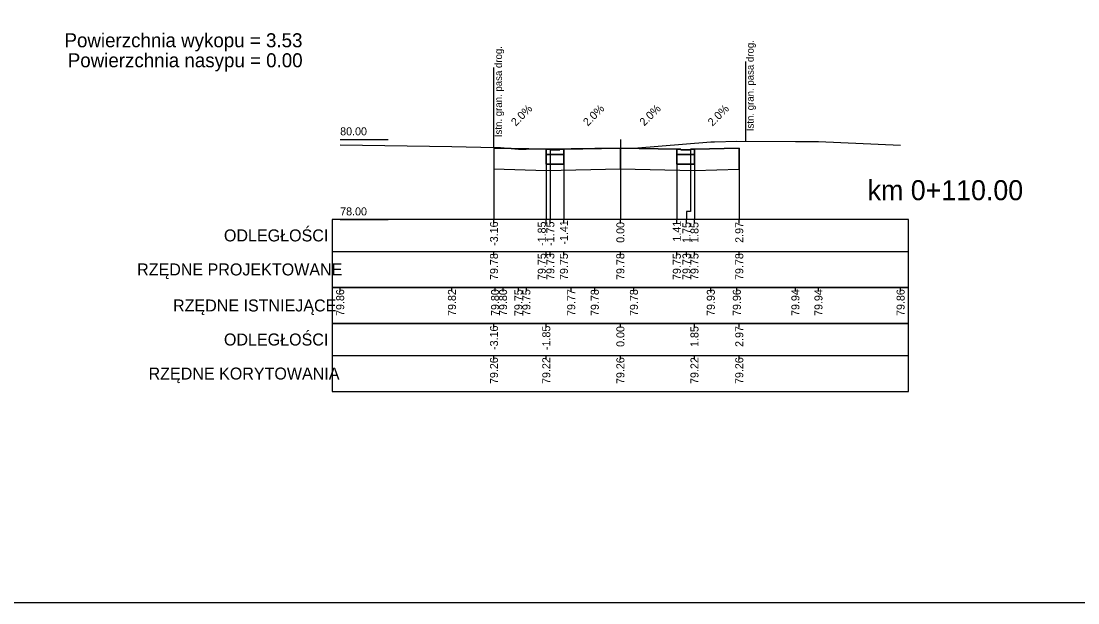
# Model space of a CAD drawing. Extents: x 7492871 to 7493499, y 5802964 to 5802992.
# Drawn here: x 7492929.58 to 7492955.98, y 5802963.88 to 5802978.41 of the extents above; entities that cross this region are included whole.
import ezdxf

# ---------------------------------------------------------------- set-up
doc = ezdxf.new("R2010")
doc.units = 0
for name, color, linetype in [('_wydruk', 7, 'Continuous'), ('d_pop_nasyp_opis', 7, 'Continuous'), ('d_pop_wykop_opis', 7, 'Continuous'), ('opisy_ramki_pop', 7, 'Continuous'), ('pop_comp_kostka', 7, 'Continuous'), ('pop_comp_lawa', 7, 'Continuous'), ('pop_comp_scieralna', 7, 'Continuous'), ('pop_granica_istn', 7, 'Continuous'), ('pop_opis', 7, 'Continuous'), ('pop_os', 7, 'Continuous'), ('pop_pikietaz', 7, 'Continuous'), ('pop_teren', 7, 'Continuous')]:
    doc.layers.add(name, color=color, linetype=linetype)

msp = doc.modelspace()

# ---------------------------------------------------------------- linework, layer by layer
msp.add_lwpolyline([(7492941.389, 5802975.239), (7492942.696, 5802975.213), (7492942.796, 5802975.213), (7492942.797, 5802975.193), (7492943.036, 5802975.193), (7492943.037, 5802975.213), (7492943.137, 5802975.213), (7492944.547, 5802975.241), (7492945.957, 5802975.213), (7492946.057, 5802975.213), (7492946.058, 5802975.193), (7492946.297, 5802975.193), (7492946.298, 5802975.213), (7492946.398, 5802975.213), (7492947.517, 5802975.235)])
at = {"layer": '_wydruk'}
msp.add_lwpolyline([(7492871.369, 5802992.281), (7493499.283, 5802992.281), (7493499.283, 5802963.881), (7492871.369, 5802963.881)], close=True, dxfattribs=at)
at = {"layer": 'opisy_ramki_pop'}
for points in [[(7492941.389, 5802974.719), (7492941.389, 5802973.659), (7492941.389, 5802973.659), (7492941.389, 5802973.459)], [(7492942.696, 5802974.684), (7492942.696, 5802973.659), (7492942.696, 5802973.659), (7492942.696, 5802973.459)], [(7492944.547, 5802974.721), (7492944.547, 5802973.659), (7492944.547, 5802973.659), (7492944.547, 5802973.459)], [(7492946.398, 5802974.684), (7492946.398, 5802973.659), (7492946.398, 5802973.659), (7492946.398, 5802973.459)], [(7492947.517, 5802974.715), (7492947.517, 5802973.659), (7492947.517, 5802973.659), (7492947.517, 5802973.459)]]:
    msp.add_lwpolyline(points, dxfattribs=at)
at = {"layer": 'pop_comp_kostka'}
for p, q in [((7492942.796, 5802975.213), (7492942.696, 5802975.213)), ((7492942.696, 5802975.213), (7492942.696, 5802975.083)), ((7492942.797, 5802975.193), (7492942.796, 5802975.213)), ((7492943.037, 5802975.213), (7492943.036, 5802975.193)), ((7492943.137, 5802975.213), (7492943.037, 5802975.213)), ((7492943.137, 5802975.083), (7492943.137, 5802975.213)), ((7492946.057, 5802975.213), (7492945.957, 5802975.213)), ((7492945.957, 5802975.213), (7492945.957, 5802975.083)), ((7492946.058, 5802975.193), (7492946.057, 5802975.213)), ((7492946.298, 5802975.213), (7492946.297, 5802975.193)), ((7492946.398, 5802975.213), (7492946.298, 5802975.213)), ((7492946.398, 5802975.083), (7492946.398, 5802975.213)), ((7492942.696, 5802975.083), (7492943.137, 5802975.083)), ((7492943.036, 5802975.193), (7492942.797, 5802975.193)), ((7492945.957, 5802975.083), (7492946.398, 5802975.083)), ((7492946.297, 5802975.193), (7492946.058, 5802975.193))]:
    msp.add_line(p, q, dxfattribs=at)
at = {"layer": 'pop_comp_lawa'}
for p, q in [((7492943.137, 5802975.083), (7492942.696, 5802975.083)), ((7492942.696, 5802975.083), (7492942.696, 5802974.842)), ((7492943.137, 5802974.842), (7492943.137, 5802975.083)), ((7492946.398, 5802975.083), (7492945.957, 5802975.083)), ((7492945.957, 5802975.083), (7492945.957, 5802974.842)), ((7492946.398, 5802974.842), (7492946.398, 5802975.083)), ((7492942.696, 5802974.842), (7492943.137, 5802974.842)), ((7492945.957, 5802974.842), (7492946.398, 5802974.842))]:
    msp.add_line(p, q, dxfattribs=at)
at = {"layer": 'pop_comp_scieralna'}
for p, q in [((7492942.696, 5802975.213), (7492941.389, 5802975.239)), ((7492941.389, 5802975.239), (7492941.389, 5802974.719)), ((7492942.696, 5802974.842), (7492942.696, 5802975.213)), ((7492944.547, 5802975.241), (7492943.137, 5802975.213)), ((7492943.137, 5802975.213), (7492943.137, 5802974.842)), ((7492944.547, 5802974.721), (7492944.547, 5802975.241)), ((7492945.957, 5802975.213), (7492944.547, 5802975.241)), ((7492944.547, 5802975.241), (7492944.547, 5802974.721)), ((7492945.957, 5802974.842), (7492945.957, 5802975.213)), ((7492947.517, 5802975.235), (7492946.398, 5802975.213)), ((7492946.398, 5802975.213), (7492946.398, 5802974.842)), ((7492947.517, 5802974.715), (7492947.517, 5802975.235)), ((7492941.389, 5802974.719), (7492942.696, 5802974.684)), ((7492943.137, 5802974.842), (7492942.696, 5802974.842)), ((7492942.696, 5802974.684), (7492944.547, 5802974.721)), ((7492944.547, 5802974.721), (7492946.398, 5802974.684)), ((7492946.398, 5802974.842), (7492945.957, 5802974.842)), ((7492946.398, 5802974.684), (7492947.517, 5802974.715))]:
    msp.add_line(p, q, dxfattribs=at)
at = {"layer": 'pop_granica_istn'}
for p, q in [((7492947.68, 5802975.902), (7492947.68, 5802977.402)), ((7492941.389, 5802975.753), (7492941.389, 5802977.253)), ((7492941.389, 5802975.253), (7492941.389, 5802975.753)), ((7492947.68, 5802975.402), (7492947.68, 5802975.902))]:
    msp.add_line(p, q, dxfattribs=at)
at = {"layer": 'pop_opis'}
for p, q in [((7492937.547, 5802975.459), (7492938.747, 5802975.459)), ((7492937.347, 5802973.459), (7492937.347, 5802971.759)), ((7492937.347, 5802973.459), (7492937.347, 5802971.759)), ((7492937.347, 5802973.459), (7492937.347, 5802971.759)), ((7492937.347, 5802973.459), (7492937.347, 5802971.759)), ((7492937.547, 5802973.459), (7492938.747, 5802973.459)), ((7492941.389, 5802973.359), (7492941.389, 5802973.459)), ((7492942.696, 5802973.359), (7492942.696, 5802973.459)), ((7492942.797, 5802973.359), (7492942.797, 5802973.459)), ((7492943.137, 5802973.359), (7492943.137, 5802973.459)), ((7492944.547, 5802973.359), (7492944.547, 5802973.459)), ((7492945.957, 5802973.359), (7492945.957, 5802973.459)), ((7492946.198, 5802973.359), (7492946.198, 5802973.459)), ((7492946.398, 5802973.359), (7492946.398, 5802973.459)), ((7492947.517, 5802973.359), (7492947.517, 5802973.459)), ((7492937.347, 5802972.659), (7492951.747, 5802972.659)), ((7492937.347, 5802972.659), (7492951.747, 5802972.659)), ((7492937.347, 5802972.659), (7492951.747, 5802972.659)), ((7492937.347, 5802972.659), (7492951.747, 5802972.659)), ((7492941.389, 5802972.559), (7492941.389, 5802972.659)), ((7492942.696, 5802972.559), (7492942.696, 5802972.659)), ((7492942.797, 5802972.559), (7492942.797, 5802972.659)), ((7492943.137, 5802972.559), (7492943.137, 5802972.659)), ((7492944.547, 5802972.559), (7492944.547, 5802972.659)), ((7492945.957, 5802972.559), (7492945.957, 5802972.659)), ((7492946.198, 5802972.559), (7492946.198, 5802972.659)), ((7492946.398, 5802972.559), (7492946.398, 5802972.659)), ((7492947.517, 5802972.559), (7492947.517, 5802972.659)), ((7492937.347, 5802971.759), (7492937.347, 5802970.859)), ((7492937.547, 5802971.659), (7492937.547, 5802971.759)), ((7492940.339, 5802971.659), (7492940.339, 5802971.759)), ((7492941.416, 5802971.659), (7492941.416, 5802971.759)), ((7492941.616, 5802971.659), (7492941.616, 5802971.759)), ((7492941.998, 5802971.659), (7492941.998, 5802971.759)), ((7492942.198, 5802971.659), (7492942.198, 5802971.759)), ((7492943.319, 5802971.659), (7492943.319, 5802971.759)), ((7492943.908, 5802971.659), (7492943.908, 5802971.759)), ((7492944.885, 5802971.659), (7492944.885, 5802971.759)), ((7492946.806, 5802971.659), (7492946.806, 5802971.759)), ((7492947.456, 5802971.659), (7492947.456, 5802971.759)), ((7492948.919, 5802971.659), (7492948.919, 5802971.759)), ((7492949.495, 5802971.659), (7492949.495, 5802971.759)), ((7492951.547, 5802971.659), (7492951.547, 5802971.759)), ((7492937.347, 5802970.859), (7492937.347, 5802969.159)), ((7492941.389, 5802970.759), (7492941.389, 5802970.859)), ((7492942.696, 5802970.759), (7492942.696, 5802970.859)), ((7492944.547, 5802970.759), (7492944.547, 5802970.859)), ((7492946.398, 5802970.759), (7492946.398, 5802970.859)), ((7492947.517, 5802970.759), (7492947.517, 5802970.859)), ((7492937.347, 5802970.059), (7492951.747, 5802970.059)), ((7492941.389, 5802969.959), (7492941.389, 5802970.059)), ((7492942.696, 5802969.959), (7492942.696, 5802970.059)), ((7492944.547, 5802969.959), (7492944.547, 5802970.059)), ((7492946.398, 5802969.959), (7492946.398, 5802970.059)), ((7492947.517, 5802969.959), (7492947.517, 5802970.059))]:
    msp.add_line(p, q, dxfattribs=at)
for points in [[(7492941.389, 5802975.239), (7492941.389, 5802973.659), (7492941.389, 5802973.659), (7492941.389, 5802973.459)], [(7492942.696, 5802975.213), (7492942.696, 5802973.659), (7492942.696, 5802973.659), (7492942.696, 5802973.459)], [(7492943.137, 5802975.213), (7492943.137, 5802973.659), (7492943.137, 5802973.659), (7492943.137, 5802973.459)], [(7492944.547, 5802975.241), (7492944.547, 5802973.659), (7492944.547, 5802973.659), (7492944.547, 5802973.459)], [(7492945.957, 5802975.213), (7492945.957, 5802973.659), (7492945.957, 5802973.659), (7492945.957, 5802973.459)], [(7492946.398, 5802975.213), (7492946.398, 5802973.659), (7492946.398, 5802973.659), (7492946.398, 5802973.459)], [(7492947.517, 5802975.235), (7492947.517, 5802973.659), (7492947.517, 5802973.659), (7492947.517, 5802973.459)], [(7492942.797, 5802975.193), (7492942.797, 5802973.659), (7492942.797, 5802973.659), (7492942.797, 5802973.459)], [(7492946.297, 5802975.193), (7492946.297, 5802973.659), (7492946.198, 5802973.659), (7492946.198, 5802973.459)]]:
    msp.add_lwpolyline(points, dxfattribs=at)
for points in [[(7492937.347, 5802973.459), (7492937.347, 5802971.759), (7492951.747, 5802971.759), (7492951.747, 5802973.459)], [(7492937.347, 5802973.459), (7492937.347, 5802971.759), (7492951.747, 5802971.759), (7492951.747, 5802973.459)], [(7492937.347, 5802973.459), (7492937.347, 5802971.759), (7492951.747, 5802971.759), (7492951.747, 5802973.459)], [(7492937.347, 5802973.459), (7492937.347, 5802971.759), (7492951.747, 5802971.759), (7492951.747, 5802973.459)], [(7492937.347, 5802971.759), (7492937.347, 5802970.859), (7492951.747, 5802970.859), (7492951.747, 5802971.759)], [(7492937.347, 5802970.859), (7492937.347, 5802969.159), (7492951.747, 5802969.159), (7492951.747, 5802970.859)]]:
    msp.add_lwpolyline(points, close=True, dxfattribs=at)
at = {"layer": 'pop_os'}
msp.add_line((7492944.547, 5802975.459), (7492944.547, 5802973.459), dxfattribs=at)
at = {"layer": 'pop_teren'}
msp.add_lwpolyline([(7492937.547, 5802975.32), (7492940.339, 5802975.283), (7492941.416, 5802975.255), (7492941.555, 5802975.255), (7492941.998, 5802975.213), (7492942.191, 5802975.21), (7492943.319, 5802975.232), (7492943.908, 5802975.235), (7492944.885, 5802975.24), (7492946.806, 5802975.393), (7492946.899, 5802975.4), (7492947.456, 5802975.416), (7492948.919, 5802975.404), (7492949.495, 5802975.403), (7492951.547, 5802975.315)], dxfattribs=at)

# ---------------------------------------------------------------- texts
at = {"layer": 'd_pop_nasyp_opis'}
msp.add_text('Powierzchnia nasypu = 0.00', height=0.35, dxfattribs=at).set_placement((7492930.742, 5802977.259))
at = {"layer": 'd_pop_wykop_opis'}
msp.add_text('Powierzchnia wykopu = 3.53', height=0.35, dxfattribs=at).set_placement((7492930.66, 5802977.759))
at = {"layer": 'pop_granica_istn'}
for p in [(7492947.878, 5802975.663), (7492941.588, 5802975.514)]:
    msp.add_text('Istn. gran. pasa drog.', height=0.18, rotation=90, dxfattribs=at).set_placement(p)
at = {"layer": 'pop_opis'}
for s, rotation, p in [('2.0%', 45, (7492941.934, 5802975.776)), ('2.0%', 45, (7492943.734, 5802975.777)), ('2.0%', 45, (7492945.144, 5802975.777)), ('2.0%', 45, (7492946.849, 5802975.774)), ('-3.16', 90, (7492941.489, 5802972.798)), ('-1.85', 90, (7492942.683, 5802972.796)), ('-1.75', 90, (7492942.897, 5802972.796)), ('-1.41', 90, (7492943.237, 5802972.829)), ('0.00', 90, (7492944.647, 5802972.874)), ('1.41', 90, (7492946.057, 5802972.905)), ('1.75', 90, (7492946.298, 5802972.873)), ('1.85', 90, (7492946.498, 5802972.873)), ('2.97', 90, (7492947.617, 5802972.874)), ('79.78', 90, (7492941.489, 5802971.946)), ('79.75', 90, (7492942.683, 5802971.945)), ('79.73', 90, (7492942.897, 5802971.947)), ('79.75', 90, (7492943.237, 5802971.945)), ('79.78', 90, (7492944.647, 5802971.946)), ('79.75', 90, (7492946.057, 5802971.945)), ('79.73', 90, (7492946.298, 5802971.947)), ('79.75', 90, (7492946.498, 5802971.945)), ('79.78', 90, (7492947.617, 5802971.946)), ('79.86', 90, (7492937.647, 5802971.047)), ('79.82', 90, (7492940.439, 5802971.048)), ('79.80', 90, (7492941.516, 5802971.047)), ('79.80', 90, (7492941.716, 5802971.047)), ('79.75', 90, (7492942.098, 5802971.045)), ('79.75', 90, (7492942.298, 5802971.045)), ('79.77', 90, (7492943.419, 5802971.047)), ('79.78', 90, (7492944.008, 5802971.046)), ('79.78', 90, (7492944.985, 5802971.046)), ('79.93', 90, (7492946.906, 5802971.047)), ('79.96', 90, (7492947.556, 5802971.047)), ('79.94', 90, (7492949.019, 5802971.047)), ('79.94', 90, (7492949.595, 5802971.047)), ('79.86', 90, (7492951.647, 5802971.047)), ('-3.16', 90, (7492941.489, 5802970.198)), ('-1.85', 90, (7492942.796, 5802970.196)), ('0.00', 90, (7492944.647, 5802970.274)), ('1.85', 90, (7492946.498, 5802970.273)), ('2.97', 90, (7492947.617, 5802970.274)), ('79.26', 90, (7492941.489, 5802969.347)), ('79.22', 90, (7492942.796, 5802969.348)), ('79.26', 90, (7492944.647, 5802969.347)), ('79.22', 90, (7492946.498, 5802969.348)), ('79.26', 90, (7492947.617, 5802969.347))]:
    msp.add_text(s, height=0.2, rotation=rotation, dxfattribs=at).set_placement(p)
for s, height, p in [('80.00', 0.2, (7492937.547, 5802975.559)), ('78.00', 0.2, (7492937.547, 5802973.559)), ('ODLEGŁOŚCI', 0.3, (7492934.643, 5802972.909)), ('ODLEGŁOŚCI', 0.3, (7492934.643, 5802972.909)), ('ODLEGŁOŚCI', 0.3, (7492934.643, 5802972.909)), ('ODLEGŁOŚCI', 0.3, (7492934.643, 5802972.909)), ('RZĘDNE PROJEKTOWANE', 0.3, (7492932.475, 5802972.059)), ('RZĘDNE PROJEKTOWANE', 0.3, (7492932.475, 5802972.059)), ('RZĘDNE PROJEKTOWANE', 0.3, (7492932.475, 5802972.059)), ('RZĘDNE PROJEKTOWANE', 0.3, (7492932.475, 5802972.059)), ('RZĘDNE ISTNIEJĄCE', 0.3, (7492933.372, 5802971.159)), ('ODLEGŁOŚCI', 0.3, (7492934.643, 5802970.309)), ('RZĘDNE KORYTOWANIA', 0.3, (7492932.761, 5802969.459))]:
    msp.add_text(s, height=height, dxfattribs=at).set_placement(p)
at = {"layer": 'pop_pikietaz'}
msp.add_text('km 0+110.00', height=0.5, dxfattribs=at).set_placement((7492950.724, 5802973.939))

doc.saveas('drawing.dxf')
